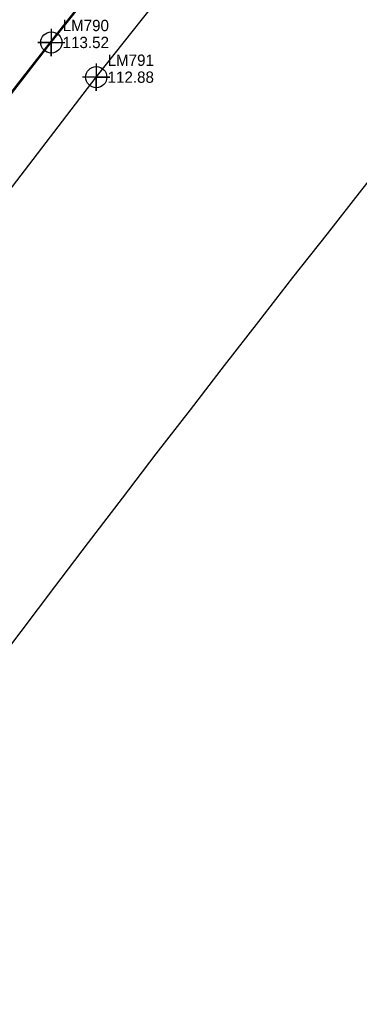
# Model space of a CAD drawing. Extents: x 2262665 to 2270527, y 505476 to 514960.
# Drawn here: x 2263549.1 to 2263624.2, y 506381 to 506595.7 of the extents above; entities that cross this region are included whole.
import ezdxf

# ---------------------------------------------------------------- set-up
doc = ezdxf.new("R2010")
doc.units = 0
for name, color, linetype in [('Exist Horizontal Alignment', 7, 'Continuous'), ('Exist Right of Way Control of Access Line', 7, 'Continuous'), ('Exist Roads EOP', 7, 'Continuous'), ('Exist Roads EOP Cogo Elevation', 7, 'Continuous'), ('Exist Roads EOP Cogo Number', 7, 'Continuous'), ('Exist Roads EOP Cogo Point CELL', 7, 'Continuous'), ('Exist Roads EOT', 7, 'Continuous'), ('Exist Roads EOT Cogo Elevation', 7, 'Continuous'), ('Exist Roads EOT Cogo Number', 7, 'Continuous'), ('Exist Roads EOT Cogo Point CELL', 7, 'Continuous')]:
    doc.layers.add(name, color=color, linetype=linetype)

msp = doc.modelspace()

# ---------------------------------------------------------------- linework, layer by layer
at = {"layer": 'Exist Horizontal Alignment'}
msp.add_arc((2268061.07, 503049.99), 5730, 127.616931, 143.020357, dxfattribs=at)
at = {"layer": 'Exist Right of Way Control of Access Line'}
msp.add_arc((2268046.88, 503073.7), 5630, 127.61693, 143.64618, dxfattribs=at)
at = {"layer": 'Exist Roads EOP'}
msp.add_lwpolyline([(2262733.48, 505545.24), (2262797.01, 505631.48), (2262859.53, 505714.33), (2262926.3, 505797.38), (2262991.13, 505875.23), (2263058.78, 505953.79), (2263118.71, 506021.87), (2263184.49, 506097.77), (2263245.68, 506170.99), (2263308.68, 506248.82), (2263369.24, 506325.05), (2263435.02, 506410.87), (2263492.86, 506487.18), (2263566.07, 506582.9), (2263633.6, 506668.21)], dxfattribs=at)
at = {"layer": 'Exist Roads EOP Cogo Point CELL'}
msp.add_lwpolyline([(2263566.07, 506585.9), (2263566.07, 506579.9), (2263566.07, 506582.9), (2263569.07, 506582.9), (2263563.07, 506582.9)], dxfattribs=at)
msp.add_circle((2263566.07, 506582.9), 2.34, dxfattribs=at)
at = {"layer": 'Exist Roads EOT'}
msp.add_lwpolyline([(2262848.91, 505722.2), (2262915.03, 505805.61), (2262981.42, 505884.81), (2263049.74, 505962.31), (2263110.41, 506031.31), (2263174.89, 506105.38), (2263236.35, 506178.72), (2263299.06, 506255.93), (2263359.29, 506331.6), (2263424.71, 506418.16), (2263482.46, 506495.16), (2263556.15, 506590.57), (2263624.13, 506675.94)], dxfattribs=at)
at = {"layer": 'Exist Roads EOT Cogo Point CELL'}
msp.add_lwpolyline([(2263556.15, 506593.57), (2263556.15, 506587.57), (2263556.15, 506590.57), (2263553.15, 506590.57), (2263559.15, 506590.57)], dxfattribs=at)
msp.add_circle((2263556.15, 506590.57), 2.34, dxfattribs=at)

# ---------------------------------------------------------------- texts
at = {"layer": 'Exist Roads EOP Cogo Elevation'}
msp.add_text('112.88', height=2.5, dxfattribs=at).set_placement((2263568.57, 506581.65))
at = {"layer": 'Exist Roads EOP Cogo Number'}
msp.add_text('LM791', height=2.5, dxfattribs=at).set_placement((2263568.57, 506585.4))
at = {"layer": 'Exist Roads EOT Cogo Elevation'}
msp.add_text('113.52', height=2.5, dxfattribs=at).set_placement((2263558.65, 506589.32))
at = {"layer": 'Exist Roads EOT Cogo Number'}
msp.add_text('LM790', height=2.5, dxfattribs=at).set_placement((2263558.65, 506593.07))

doc.saveas('drawing.dxf')
